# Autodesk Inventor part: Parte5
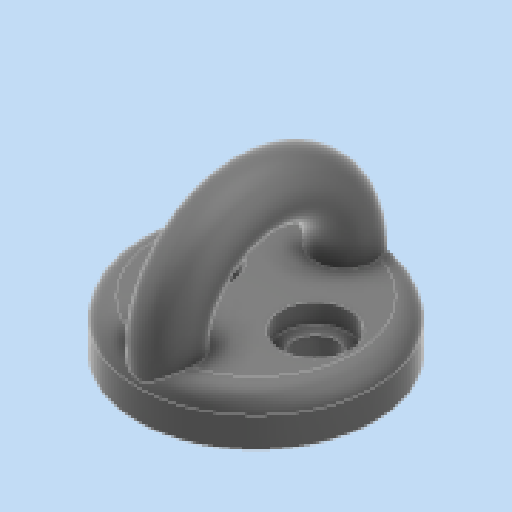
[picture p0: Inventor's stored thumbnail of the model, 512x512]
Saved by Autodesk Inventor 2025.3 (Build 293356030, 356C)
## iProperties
Created: 2026-05
Part Number: Parte5
Material: Generico
Document SubType Name: Modeling
Designer: R5800u
Density: 1 g/cm^3
Appearance: Liscia - Nero
Author: R5800u
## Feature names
1. Estrusione1 [Extrusion]
2. Foro1 [Hole]
3. Sweep1
4. Raccordo1 [Fillet]
## Parameters: d0 = 12 mm, d1 = 2.5 mm, d2 = 0, d3 = 8 mm, d4 = 2.5 mm, d5 = 2.5 mm, d6 = 1.8 mm, d7 = 6 mm, d8 = 3 mm, d9 = 1 mm, d10 = 90 deg, d11 = 15 mm, d12 = 118 deg, d13 = 3 mm, d14 = 1.5 mm, d15 = 0, d16 = 0, d17 = 1 mm
